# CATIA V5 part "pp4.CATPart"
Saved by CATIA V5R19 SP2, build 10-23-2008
Part number: pp4
Publications: "Line.1", "Line.2", "Line.3", "Point.3", "Point.4", "Plane.1", "Line.8", "Line.9", "Line.10", "Line.11", "Plane.2"
Bounding box of the stored display mesh (mm): x 0 to 10, y -130 to 0, z -50 to 50
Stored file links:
  C:\Users\Welcome\Documents\thinkm2\pp4.CATPart
  C:\Users\Welcome\Documents\thinkm2\Brasmeca.CATProduct
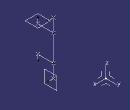
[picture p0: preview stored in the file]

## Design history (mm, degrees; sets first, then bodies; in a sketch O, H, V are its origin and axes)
AxisSystem1: origin (0, 0, 0), X (1, 0, 0), Y (0, 1, 0), Z (0, 0, 1)
Set1
  Point1 to Point4: linked copy from another document
Body1 (main body)
  Line1: type PtPt, FirstPoint Point1, SecondPoint Point2
  Line2: type PtDir, RefPoint Point1, Direction edge [XY plane of AxisSystem1 | ZX plane of AxisSystem1], Start 0, End 10
  Line3: type PtDir, RefPoint Point2, Direction edge [XY plane of AxisSystem1 | ZX plane of AxisSystem1], Start 0, End 10
  Point5: type OnCurve, Support Line1, Length 25
  Point6: type OnCurve, Support Line1, Length 75
  Plane1: type Normal, Curve Line3
  Line4: type PtPt, FirstPoint Point5, SecondPoint Point3
  Line5: type PtPt, FirstPoint Point6, SecondPoint Point4
  Line6: type PtDir, RefPoint Point3, Direction edge [ZX plane of AxisSystem1 | YZ plane of AxisSystem1], Start 0, End 10
  Line7: type PtDir, RefPoint Point4, Direction edge [ZX plane of AxisSystem1 | YZ plane of AxisSystem1], Start 0, End -10
  Plane2: type Normal, Curve Line6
